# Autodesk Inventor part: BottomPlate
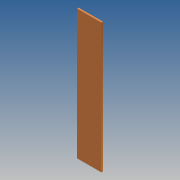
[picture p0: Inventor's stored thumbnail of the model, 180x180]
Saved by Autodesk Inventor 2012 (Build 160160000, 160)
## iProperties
Created: 2007-12
Part Number: BottomPlate
Document SubType Name: Modeling
Designer: MJ
Stock Number: D-623-012-b
Material: Aluminum-6061
Density: 2.71 g/cm^3
Engineer: MJ
Mass: 3197.44 g
Surface Area: 2661.28 cm^2
Volume: 1179.87 cm^3
RuleStatus: InUse
Title: DgPr Assembly Cell
Author: MJ
Comments: 1/4" X 6" X 44.12"
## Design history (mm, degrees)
sketch "Sketch1"
  geometry: L1 (-76.2, 406.4)-(76.2, 406.4); L2 (76.2, 406.4)-(76.2, -406.4); L3 (76.2, -406.4)-(-76.2, -406.4); L4 (-76.2, -406.4)-(-76.2, 406.4); L5 (76.2, -406.4)-(-76.2, 406.4); 2 further points
  constraints: 10 end point, 4 parallel, 1 coincident, 1 horizontal, 1 midpoint, 1 perpendicular
extrude "Extrusion1" new body sketch "Sketch1" taper "d3" = 0 deg
body "Solid1"
